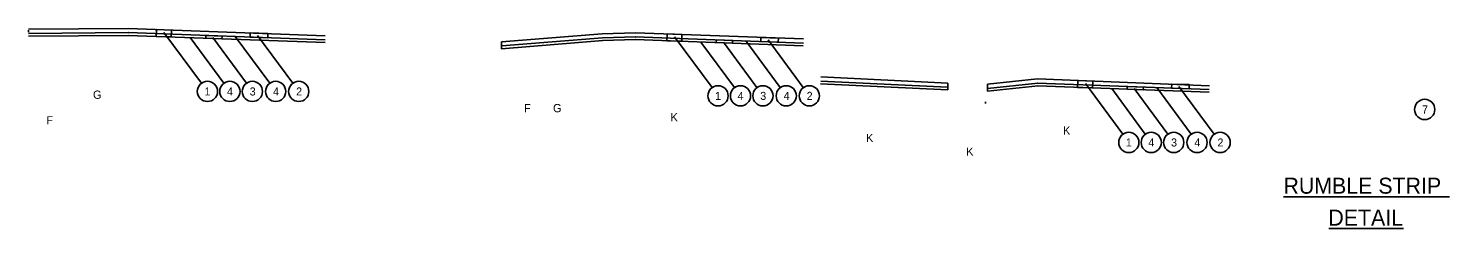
# Model space of a CAD drawing. Extents: x -210 to 558, y -150 to 205.
# Drawn here: x -209.3 to -112.2, y 51.6 to 65.2 of the extents above; entities that cross this region are included whole.
import ezdxf

# ---------------------------------------------------------------- set-up
doc = ezdxf.new("R2010")
doc.units = 0
for name, color, linetype in [('Level 1', 7, 'Continuous'), ('Level 3', 7, 'Continuous'), ('Level 59', 7, 'Continuous')]:
    doc.layers.add(name, color=color, linetype=linetype)

msp = doc.modelspace()

# ---------------------------------------------------------------- linework, layer by layer
at = {"layer": 'Level 1'}
for p, q in [((-202.435, 65.217), (-209.262, 65.157)), ((-209.261, 65.092), (-209.261, 64.957)), ((-188.976, 64.717), (-202.432, 65.217)), ((-202.433, 64.935), (-209.259, 64.874)), ((-202.431, 64.747), (-209.258, 64.686)), ((-188.993, 64.247), (-202.45, 64.747)), ((-188.986, 64.435), (-202.443, 64.935)), ((-197.44, 61.475), (-199.999, 64.95)), ((-195.905, 61.475), (-198.199, 64.589)), ((-194.371, 61.475), (-196.665, 64.589)), ((-192.777, 61.475), (-195.125, 64.663)), ((-191.2, 61.475), (-193.601, 64.734)), ((-176.939, 64.302), (-170.053, 64.851)), ((-176.939, 63.835), (-170.016, 64.387)), ((-176.939, 64.302), (-176.939, 63.835)), ((-176.916, 64.025), (-170.031, 64.574)), ((-170.053, 64.851), (-167.787, 64.923)), ((-170.044, 64.573), (-167.778, 64.645)), ((-170.038, 64.385), (-167.772, 64.457)), ((-156.313, 64.03), (-167.804, 64.456)), ((-156.306, 64.217), (-167.797, 64.644)), ((-167.787, 64.923), (-156.295, 64.51)), ((-162.552, 61.176), (-165.112, 64.65)), ((-161.018, 61.176), (-163.312, 64.29)), ((-159.484, 61.176), (-161.777, 64.29)), ((-157.89, 61.176), (-160.238, 64.364)), ((-156.313, 61.176), (-158.714, 64.434)), ((-155.137, 61.445), (-146.441, 61.023)), ((-155.128, 61.625), (-146.455, 61.204)), ((-155.115, 61.904), (-146.441, 61.484)), ((-146.441, 61.484), (-146.441, 61.023)), ((-140.312, 61.775), (-143.734, 61.409)), ((-140.281, 61.486), (-143.734, 61.117)), ((-143.734, 61.409), (-143.734, 60.928)), ((-140.261, 61.3), (-143.734, 60.928)), ((-128.564, 61.298), (-140.312, 61.775)), ((-128.574, 61.047), (-140.312, 61.483)), ((-128.581, 60.859), (-140.312, 61.295)), ((-134.484, 57.993), (-137.043, 61.467)), ((-129.821, 57.993), (-132.169, 61.181)), ((-128.245, 57.993), (-130.645, 61.252)), ((-143.855, 60.218), (-143.855, 60.093)), ((-132.949, 57.993), (-135.243, 61.107)), ((-131.415, 57.993), (-133.709, 61.107))]:
    msp.add_line(p, q, dxfattribs=at)
for points in [[(-199.511, 64.638), (-200.532, 64.676), (-200.514, 65.146), (-199.494, 65.108)], [(-197.148, 64.55), (-196.038, 64.509), (-196.031, 64.697), (-197.141, 64.738)], [(-194.11, 64.626), (-192.908, 64.581), (-192.897, 64.863), (-194.099, 64.908)], [(-164.624, 64.338), (-165.644, 64.376), (-165.627, 64.846), (-164.607, 64.808)], [(-162.261, 64.251), (-161.151, 64.209), (-161.144, 64.397), (-162.254, 64.438)], [(-159.223, 64.326), (-158.021, 64.281), (-158.01, 64.563), (-159.212, 64.608)], [(-136.556, 61.155), (-137.576, 61.193), (-137.558, 61.663), (-136.538, 61.625)], [(-134.193, 61.068), (-133.082, 61.026), (-133.075, 61.214), (-134.186, 61.256)], [(-131.154, 61.143), (-129.952, 61.098), (-129.941, 61.38), (-131.143, 61.425)]]:
    msp.add_lwpolyline(points, close=True, dxfattribs=at)
for centre in [(-197.03, 60.919), (-195.495, 60.919), (-193.961, 60.919), (-192.367, 60.919), (-190.79, 60.919), (-162.142, 60.619), (-160.608, 60.619), (-159.074, 60.619), (-157.48, 60.619), (-155.903, 60.619), (-113.856, 59.689), (-134.074, 57.436), (-132.539, 57.436), (-131.005, 57.436), (-129.411, 57.436), (-127.835, 57.436)]:
    msp.add_circle(centre, 0.691, dxfattribs=at)
at = {"layer": 'Level 59'}
for p, q in [((-123.493, 53.732), (-112.155, 53.732)), ((-120.402, 51.558), (-115.299, 51.558))]:
    msp.add_line(p, q, dxfattribs=at)

# ---------------------------------------------------------------- texts
at = {"layer": 'Level 1'}
for s, p in [('1', (-197.23, 60.641)), ('4', (-195.696, 60.641)), ('3', (-194.142, 60.641)), ('4', (-192.548, 60.641)), ('2', (-190.972, 60.641)), ('1', (-162.343, 60.341)), ('4', (-160.809, 60.341)), ('3', (-159.255, 60.341)), ('4', (-157.661, 60.341)), ('2', (-156.084, 60.341)), ('7', (-114.037, 59.411)), ('1', (-134.275, 57.159)), ('4', (-132.74, 57.159)), ('3', (-131.186, 57.159)), ('4', (-129.593, 57.159)), ('2', (-128.016, 57.159))]:
    msp.add_text(s, height=0.547, dxfattribs=at).set_placement(p)
at = {"layer": 'Level 3'}
for s, p in [('G', (-204.849, 60.415)), ('F', (-175.4, 59.497)), ('G', (-173.416, 59.497)), ('K', (-165.386, 58.875)), ('F', (-208.038, 58.664)), ('K', (-138.57, 57.965)), ('K', (-152.027, 57.459)), ('K', (-145.182, 56.525))]:
    msp.add_text(s, height=0.562, dxfattribs=at).set_placement(p)
at = {"layer": 'Level 59'}
for s, height, p in [('RUMBLE STRIP', 1.09074, (-123.507, 53.939)), ('DETAIL', 1.0907, (-120.439, 51.758))]:
    msp.add_text(s, height=height, dxfattribs=at).set_placement(p)

doc.saveas('drawing.dxf')
